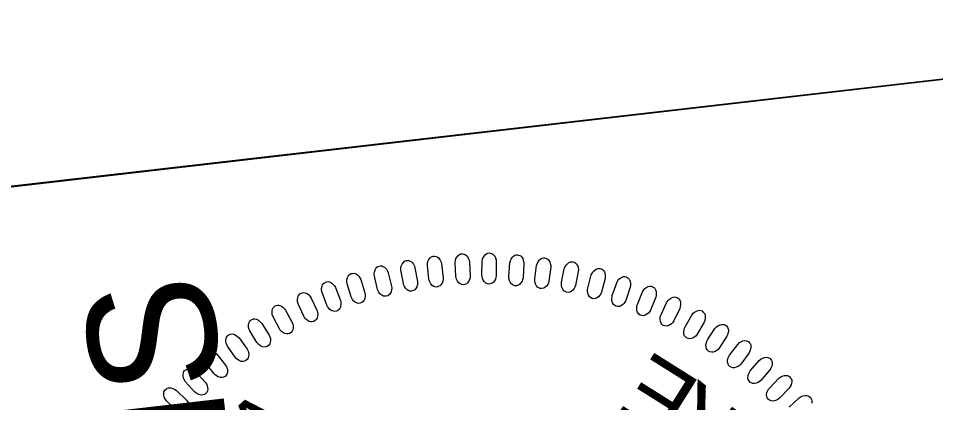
# Model space of a CAD drawing. Extents: x 477658 to 478938, y 495105 to 496902.
# Drawn here: x 477747.5 to 477830, y 496750.8 to 496785.4 of the extents above; entities that cross this region are included whole.
import ezdxf

# ---------------------------------------------------------------- set-up
doc = ezdxf.new("R2010")
doc.units = 0
for name, color, linetype in [('Sheet PE Seal Cell', 7, 'Continuous'), ('Sheet Plan CELL', 7, 'Continuous'), ('Sheet Sticker Incomplete CELL', 7, 'Continuous')]:
    doc.layers.add(name, color=color, linetype=linetype)

msp = doc.modelspace()

# ---------------------------------------------------------------- linework, layer by layer
at = {"layer": 'Sheet PE Seal Cell'}
for points in [[(477786.861, 496762.163), (477786.797, 496763.389), (477786.824, 496763.609), (477786.868, 496763.752), (477786.972, 496763.927), (477787.063, 496764.042), (477787.171, 496764.127), (477787.273, 496764.172), (477787.385, 496764.198), (477787.497, 496764.183), (477787.618, 496764.16), (477787.726, 496764.106), (477787.835, 496764.011), (477787.899, 496763.935), (477787.974, 496763.789), (477788.043, 496763.612), (477788.074, 496763.454), (477788.146, 496762.2), (477788.132, 496762.03), (477788.094, 496761.888), (477788.014, 496761.724), (477787.909, 496761.579), (477787.816, 496761.494), (477787.662, 496761.426), (477787.513, 496761.398), (477787.362, 496761.431), (477787.255, 496761.475), (477787.124, 496761.568), (477786.995, 496761.731), (477786.919, 496761.907), (477786.883, 496762.034)], [(477789.204, 496762.266), (477789.218, 496763.493), (477789.258, 496763.712), (477789.311, 496763.851), (477789.425, 496764.02), (477789.524, 496764.128), (477789.637, 496764.206), (477789.742, 496764.245), (477789.855, 496764.263), (477789.966, 496764.242), (477790.086, 496764.211), (477790.189, 496764.15), (477790.293, 496764.049), (477790.352, 496763.969), (477790.418, 496763.818), (477790.475, 496763.638), (477790.496, 496763.478), (477790.489, 496762.222), (477790.465, 496762.052), (477790.418, 496761.913), (477790.327, 496761.755), (477790.214, 496761.617), (477790.115, 496761.538), (477789.958, 496761.48), (477789.808, 496761.462), (477789.659, 496761.503), (477789.555, 496761.554), (477789.429, 496761.655), (477789.312, 496761.826), (477789.246, 496762.007), (477789.218, 496762.136)], [(477791.621, 496762.145), (477791.712, 496763.368), (477791.765, 496763.584), (477791.827, 496763.72), (477791.952, 496763.881), (477792.057, 496763.983), (477792.175, 496764.054), (477792.282, 496764.086), (477792.396, 496764.098), (477792.506, 496764.07), (477792.623, 496764.031), (477792.723, 496763.964), (477792.82, 496763.856), (477792.874, 496763.772), (477792.93, 496763.618), (477792.976, 496763.435), (477792.987, 496763.274), (477792.901, 496762.021), (477792.866, 496761.853), (477792.811, 496761.717), (477792.71, 496761.565), (477792.588, 496761.434), (477792.485, 496761.361), (477792.324, 496761.313), (477792.173, 496761.304), (477792.027, 496761.355), (477791.926, 496761.413), (477791.807, 496761.521), (477791.701, 496761.699), (477791.646, 496761.884), (477791.627, 496762.015)], [(477782.134, 496761.502), (477781.918, 496762.709), (477781.917, 496762.931), (477781.943, 496763.078), (477782.024, 496763.265), (477782.1, 496763.39), (477782.197, 496763.488), (477782.292, 496763.546), (477782.399, 496763.585), (477782.513, 496763.586), (477782.636, 496763.577), (477782.749, 496763.537), (477782.87, 496763.457), (477782.943, 496763.389), (477783.036, 496763.254), (477783.127, 496763.087), (477783.176, 496762.935), (477783.405, 496761.699), (477783.413, 496761.528), (477783.393, 496761.383), (477783.333, 496761.21), (477783.248, 496761.053), (477783.166, 496760.957), (477783.022, 496760.87), (477782.878, 496760.824), (477782.725, 496760.837), (477782.612, 496760.868), (477782.47, 496760.944), (477782.323, 496761.089), (477782.224, 496761.254), (477782.172, 496761.377)], [(477784.432, 496761.917), (477784.292, 496763.136), (477784.305, 496763.358), (477784.34, 496763.502), (477784.432, 496763.684), (477784.516, 496763.804), (477784.619, 496763.896), (477784.718, 496763.947), (477784.828, 496763.98), (477784.941, 496763.973), (477785.063, 496763.957), (477785.174, 496763.909), (477785.289, 496763.822), (477785.358, 496763.75), (477785.442, 496763.609), (477785.522, 496763.437), (477785.562, 496763.282), (477785.713, 496762.034), (477785.71, 496761.863), (477785.681, 496761.719), (477785.61, 496761.55), (477785.515, 496761.399), (477785.428, 496761.308), (477785.279, 496761.231), (477785.132, 496761.194), (477784.979, 496761.217), (477784.87, 496761.255), (477784.732, 496761.339), (477784.594, 496761.494), (477784.507, 496761.664), (477784.462, 496761.79)], [(477793.96, 496761.931), (477794.128, 496763.146), (477794.195, 496763.358), (477794.265, 496763.489), (477794.4, 496763.642), (477794.511, 496763.737), (477794.633, 496763.801), (477794.742, 496763.826), (477794.856, 496763.83), (477794.964, 496763.796), (477795.079, 496763.75), (477795.174, 496763.676), (477795.264, 496763.563), (477795.313, 496763.476), (477795.359, 496763.318), (477795.394, 496763.133), (477795.394, 496762.972), (477795.23, 496761.726), (477795.184, 496761.56), (477795.121, 496761.428), (477795.011, 496761.283), (477794.88, 496761.16), (477794.774, 496761.094), (477794.609, 496761.056), (477794.458, 496761.056), (477794.316, 496761.116), (477794.219, 496761.18), (477794.106, 496761.296), (477794.012, 496761.48), (477793.969, 496761.668), (477793.958, 496761.8)], [(477796.377, 496761.633), (477796.62, 496762.836), (477796.701, 496763.043), (477796.779, 496763.17), (477796.923, 496763.314), (477797.04, 496763.402), (477797.166, 496763.458), (477797.276, 496763.476), (477797.39, 496763.473), (477797.496, 496763.431), (477797.607, 496763.378), (477797.698, 496763.299), (477797.78, 496763.18), (477797.823, 496763.09), (477797.859, 496762.93), (477797.883, 496762.743), (477797.873, 496762.582), (477797.631, 496761.349), (477797.575, 496761.187), (477797.503, 496761.059), (477797.384, 496760.92), (477797.247, 496760.806), (477797.136, 496760.747), (477796.97, 496760.719), (477796.819, 496760.73), (477796.681, 496760.798), (477796.588, 496760.868), (477796.483, 496760.991), (477796.4, 496761.181), (477796.369, 496761.37), (477796.366, 496761.503)], [(477777.436, 496760.314), (477777.07, 496761.485), (477777.04, 496761.705), (477777.048, 496761.854), (477777.105, 496762.05), (477777.165, 496762.183), (477777.248, 496762.293), (477777.336, 496762.362), (477777.437, 496762.415), (477777.549, 496762.429), (477777.673, 496762.436), (477777.79, 496762.41), (477777.92, 496762.346), (477778.001, 496762.288), (477778.11, 496762.165), (477778.221, 496762.012), (477778.29, 496761.866), (477778.672, 496760.669), (477778.701, 496760.5), (477778.699, 496760.354), (477778.661, 496760.175), (477778.596, 496760.008), (477778.528, 496759.903), (477778.395, 496759.799), (477778.258, 496759.735), (477778.104, 496759.729), (477777.989, 496759.745), (477777.838, 496759.802), (477777.674, 496759.929), (477777.555, 496760.08), (477777.489, 496760.195)], [(477779.813, 496760.989), (477779.522, 496762.181), (477779.506, 496762.402), (477779.523, 496762.55), (477779.592, 496762.742), (477779.66, 496762.872), (477779.749, 496762.976), (477779.842, 496763.04), (477779.946, 496763.085), (477780.06, 496763.093), (477780.183, 496763.092), (477780.299, 496763.059), (477780.424, 496762.987), (477780.501, 496762.924), (477780.602, 496762.794), (477780.704, 496762.634), (477780.763, 496762.484), (477781.069, 496761.265), (477781.087, 496761.096), (477781.077, 496760.949), (477781.028, 496760.773), (477780.952, 496760.611), (477780.877, 496760.51), (477780.739, 496760.414), (477780.598, 496760.36), (477780.443, 496760.363), (477780.33, 496760.387), (477780.183, 496760.453), (477780.026, 496760.589), (477779.919, 496760.748), (477779.859, 496760.867)], [(477798.732, 496761.098), (477799.05, 496762.283), (477799.143, 496762.485), (477799.229, 496762.606), (477799.382, 496762.741), (477799.505, 496762.822), (477799.634, 496762.869), (477799.745, 496762.88), (477799.858, 496762.871), (477799.961, 496762.823), (477800.069, 496762.763), (477800.155, 496762.678), (477800.23, 496762.554), (477800.267, 496762.461), (477800.293, 496762.3), (477800.304, 496762.111), (477800.284, 496761.951), (477799.965, 496760.735), (477799.9, 496760.578), (477799.82, 496760.454), (477799.692, 496760.324), (477799.548, 496760.218), (477799.433, 496760.165), (477799.266, 496760.149), (477799.117, 496760.168), (477798.982, 496760.246), (477798.894, 496760.321), (477798.797, 496760.45), (477798.727, 496760.645), (477798.708, 496760.837), (477798.713, 496760.969)], [(477775.254, 496759.55), (477774.816, 496760.695), (477774.773, 496760.913), (477774.771, 496761.062), (477774.815, 496761.261), (477774.866, 496761.398), (477774.943, 496761.513), (477775.026, 496761.587), (477775.124, 496761.646), (477775.236, 496761.668), (477775.358, 496761.682), (477775.477, 496761.664), (477775.61, 496761.608), (477775.695, 496761.555), (477775.811, 496761.439), (477775.932, 496761.293), (477776.01, 496761.152), (477776.466, 496759.982), (477776.505, 496759.815), (477776.513, 496759.669), (477776.487, 496759.488), (477776.432, 496759.317), (477776.37, 496759.208), (477776.245, 496759.096), (477776.112, 496759.024), (477775.958, 496759.008), (477775.843, 496759.017), (477775.689, 496759.064), (477775.517, 496759.18), (477775.389, 496759.324), (477775.315, 496759.434)], [(477800.941, 496760.424), (477801.333, 496761.587), (477801.439, 496761.782), (477801.533, 496761.898), (477801.693, 496762.023), (477801.82, 496762.096), (477801.952, 496762.136), (477802.064, 496762.14), (477802.176, 496762.123), (477802.276, 496762.068), (477802.38, 496762.001), (477802.46, 496761.912), (477802.527, 496761.784), (477802.559, 496761.689), (477802.575, 496761.526), (477802.574, 496761.337), (477802.544, 496761.178), (477802.15, 496759.985), (477802.074, 496759.831), (477801.987, 496759.713), (477801.851, 496759.591), (477801.7, 496759.495), (477801.583, 496759.45), (477801.415, 496759.444), (477801.266, 496759.473), (477801.138, 496759.558), (477801.055, 496759.639), (477800.966, 496759.774), (477800.907, 496759.973), (477800.9, 496760.165), (477800.914, 496760.297)], [(477803.195, 496759.629), (477803.659, 496760.764), (477803.777, 496760.953), (477803.878, 496761.063), (477804.046, 496761.177), (477804.178, 496761.242), (477804.312, 496761.273), (477804.423, 496761.271), (477804.535, 496761.246), (477804.631, 496761.186), (477804.73, 496761.112), (477804.804, 496761.018), (477804.863, 496760.886), (477804.889, 496760.789), (477804.894, 496760.625), (477804.881, 496760.436), (477804.842, 496760.281), (477804.374, 496759.114), (477804.289, 496758.966), (477804.194, 496758.853), (477804.051, 496758.74), (477803.894, 496758.653), (477803.774, 496758.616), (477803.606, 496758.62), (477803.46, 496758.658), (477803.337, 496758.752), (477803.259, 496758.838), (477803.179, 496758.978), (477803.132, 496759.179), (477803.138, 496759.372), (477803.159, 496759.503)], [(477773.181, 496758.56), (477772.671, 496759.677), (477772.614, 496759.892), (477772.603, 496760.041), (477772.635, 496760.241), (477772.678, 496760.381), (477772.747, 496760.501), (477772.825, 496760.58), (477772.919, 496760.645), (477773.029, 496760.673), (477773.15, 496760.696), (477773.27, 496760.685), (477773.407, 496760.638), (477773.495, 496760.59), (477773.619, 496760.482), (477773.747, 496760.344), (477773.834, 496760.208), (477774.363, 496759.068), (477774.413, 496758.905), (477774.43, 496758.759), (477774.415, 496758.577), (477774.371, 496758.403), (477774.316, 496758.29), (477774.198, 496758.17), (477774.07, 496758.09), (477773.917, 496758.064), (477773.802, 496758.066), (477773.644, 496758.104), (477773.466, 496758.208), (477773.329, 496758.343), (477773.248, 496758.449)], [(477805.324, 496758.73), (477805.858, 496759.834), (477805.988, 496760.015), (477806.095, 496760.118), (477806.27, 496760.222), (477806.405, 496760.278), (477806.541, 496760.301), (477806.653, 496760.291), (477806.763, 496760.26), (477806.854, 496760.194), (477806.949, 496760.114), (477807.017, 496760.015), (477807.068, 496759.879), (477807.087, 496759.781), (477807.082, 496759.617), (477807.058, 496759.43), (477807.009, 496759.276), (477806.467, 496758.142), (477806.373, 496758), (477806.272, 496757.894), (477806.122, 496757.789), (477805.96, 496757.712), (477805.838, 496757.683), (477805.671, 496757.697), (477805.527, 496757.745), (477805.41, 496757.846), (477805.338, 496757.936), (477805.266, 496758.081), (477805.233, 496758.286), (477805.251, 496758.477), (477805.28, 496758.607)], [(477770.982, 496757.427), (477770.403, 496758.509), (477770.333, 496758.72), (477770.313, 496758.867), (477770.331, 496759.07), (477770.366, 496759.213), (477770.427, 496759.336), (477770.5, 496759.42), (477770.59, 496759.491), (477770.698, 496759.526), (477770.818, 496759.556), (477770.938, 496759.553), (477771.078, 496759.514), (477771.168, 496759.472), (477771.298, 496759.372), (477771.436, 496759.242), (477771.53, 496759.112), (477772.13, 496758.007), (477772.19, 496757.848), (477772.217, 496757.703), (477772.213, 496757.52), (477772.18, 496757.344), (477772.132, 496757.228), (477772.021, 496757.101), (477771.899, 496757.013), (477771.749, 496756.978), (477771.633, 496756.972), (477771.473, 496757), (477771.288, 496757.093), (477771.144, 496757.22), (477771.057, 496757.32)], [(477807.482, 496757.609), (477808.085, 496758.677), (477808.225, 496758.849), (477808.339, 496758.946), (477808.52, 496759.038), (477808.659, 496759.086), (477808.796, 496759.101), (477808.906, 496759.084), (477809.014, 496759.046), (477809.101, 496758.973), (477809.191, 496758.888), (477809.253, 496758.786), (477809.294, 496758.647), (477809.308, 496758.548), (477809.293, 496758.384), (477809.257, 496758.198), (477809.198, 496758.048), (477808.587, 496756.951), (477808.484, 496756.814), (477808.376, 496756.715), (477808.22, 496756.62), (477808.054, 496756.553), (477807.93, 496756.531), (477807.763, 496756.556), (477807.624, 496756.613), (477807.513, 496756.721), (477807.446, 496756.816), (477807.384, 496756.965), (477807.363, 496757.171), (477807.394, 496757.361), (477807.431, 496757.488)], [(477768.948, 496756.207), (477768.302, 496757.25), (477768.218, 496757.456), (477768.189, 496757.602), (477768.195, 496757.805), (477768.22, 496757.95), (477768.274, 496758.077), (477768.341, 496758.166), (477768.427, 496758.242), (477768.532, 496758.284), (477768.65, 496758.321), (477768.77, 496758.326), (477768.912, 496758.296), (477769.004, 496758.259), (477769.141, 496758.167), (477769.285, 496758.046), (477769.389, 496757.922), (477770.057, 496756.858), (477770.126, 496756.702), (477770.162, 496756.559), (477770.169, 496756.377), (477770.148, 496756.199), (477770.107, 496756.08), (477770.005, 496755.946), (477769.888, 496755.851), (477769.741, 496755.806), (477769.625, 496755.794), (477769.464, 496755.811), (477769.274, 496755.893), (477769.122, 496756.01), (477769.028, 496756.105)], [(477809.511, 496756.429), (477810.18, 496757.457), (477810.33, 496757.62), (477810.45, 496757.709), (477810.637, 496757.79), (477810.778, 496757.829), (477810.916, 496757.835), (477811.025, 496757.811), (477811.13, 496757.766), (477811.212, 496757.689), (477811.297, 496757.598), (477811.352, 496757.492), (477811.385, 496757.35), (477811.392, 496757.251), (477811.367, 496757.089), (477811.319, 496756.906), (477811.251, 496756.76), (477810.572, 496755.702), (477810.461, 496755.573), (477810.347, 496755.48), (477810.185, 496755.395), (477810.015, 496755.339), (477809.89, 496755.326), (477809.725, 496755.361), (477809.59, 496755.426), (477809.486, 496755.541), (477809.426, 496755.64), (477809.373, 496755.792), (477809.365, 496755.999), (477809.407, 496756.187), (477809.452, 496756.312)], [(477767.005, 496754.868), (477766.295, 496755.868), (477766.199, 496756.069), (477766.16, 496756.213), (477766.153, 496756.416), (477766.169, 496756.562), (477766.215, 496756.692), (477766.278, 496756.785), (477766.357, 496756.866), (477766.46, 496756.915), (477766.575, 496756.959), (477766.695, 496756.972), (477766.838, 496756.951), (477766.933, 496756.92), (477767.074, 496756.837), (477767.227, 496756.725), (477767.338, 496756.608), (477768.071, 496755.588), (477768.151, 496755.436), (477768.195, 496755.296), (477768.214, 496755.114), (477768.203, 496754.936), (477768.171, 496754.814), (477768.077, 496754.675), (477767.966, 496754.572), (477767.822, 496754.518), (477767.707, 496754.498), (477767.546, 496754.506), (477767.35, 496754.575), (477767.191, 496754.683), (477767.092, 496754.771)], [(477811.492, 496755.052), (477812.225, 496756.037), (477812.386, 496756.19), (477812.511, 496756.271), (477812.702, 496756.34), (477812.845, 496756.37), (477812.983, 496756.367), (477813.091, 496756.337), (477813.193, 496756.286), (477813.271, 496756.203), (477813.349, 496756.107), (477813.397, 496755.998), (477813.421, 496755.855), (477813.422, 496755.755), (477813.387, 496755.595), (477813.328, 496755.415), (477813.251, 496755.273), (477812.506, 496754.261), (477812.387, 496754.138), (477812.267, 496754.053), (477812.101, 496753.979), (477811.928, 496753.933), (477811.802, 496753.928), (477811.64, 496753.972), (477811.508, 496754.047), (477811.412, 496754.168), (477811.358, 496754.271), (477811.315, 496754.426), (477811.321, 496754.633), (477811.374, 496754.818), (477811.427, 496754.939)], [(477765.113, 496753.38), (477764.342, 496754.334), (477764.233, 496754.529), (477764.185, 496754.67), (477764.166, 496754.872), (477764.173, 496755.019), (477764.21, 496755.151), (477764.266, 496755.248), (477764.341, 496755.334), (477764.44, 496755.389), (477764.552, 496755.441), (477764.671, 496755.46), (477764.816, 496755.448), (477764.912, 496755.424), (477765.059, 496755.35), (477765.218, 496755.248), (477765.335, 496755.138), (477766.132, 496754.166), (477766.22, 496754.02), (477766.273, 496753.883), (477766.304, 496753.702), (477766.305, 496753.523), (477766.279, 496753.4), (477766.195, 496753.255), (477766.091, 496753.146), (477765.95, 496753.083), (477765.837, 496753.056), (477765.675, 496753.053), (477765.476, 496753.109), (477765.311, 496753.207), (477765.206, 496753.289)], [(477813.36, 496753.645), (477814.152, 496754.581), (477814.323, 496754.725), (477814.453, 496754.798), (477814.648, 496754.855), (477814.793, 496754.876), (477814.93, 496754.864), (477815.036, 496754.827), (477815.135, 496754.769), (477815.207, 496754.682), (477815.279, 496754.582), (477815.321, 496754.469), (477815.336, 496754.325), (477815.33, 496754.225), (477815.285, 496754.068), (477815.214, 496753.891), (477815.128, 496753.756), (477814.322, 496752.791), (477814.195, 496752.677), (477814.07, 496752.599), (477813.9, 496752.535), (477813.724, 496752.501), (477813.598, 496752.503), (477813.439, 496752.558), (477813.313, 496752.64), (477813.225, 496752.767), (477813.177, 496752.873), (477813.144, 496753.031), (477813.162, 496753.237), (477813.227, 496753.418), (477813.287, 496753.536)], [(477763.34, 496751.766), (477762.511, 496752.67), (477762.39, 496752.857), (477762.334, 496752.995), (477762.302, 496753.196), (477762.299, 496753.342), (477762.328, 496753.476), (477762.378, 496753.577), (477762.447, 496753.668), (477762.543, 496753.729), (477762.651, 496753.787), (477762.769, 496753.814), (477762.913, 496753.811), (477763.012, 496753.793), (477763.163, 496753.728), (477763.328, 496753.637), (477763.452, 496753.535), (477764.308, 496752.614), (477764.405, 496752.474), (477764.467, 496752.34), (477764.509, 496752.163), (477764.521, 496751.983), (477764.503, 496751.859), (477764.428, 496751.709), (477764.331, 496751.593), (477764.194, 496751.521), (477764.084, 496751.488), (477763.922, 496751.475), (477763.72, 496751.519), (477763.549, 496751.605), (477763.439, 496751.681)], [(477815.078, 496752.099), (477815.928, 496752.984), (477816.106, 496753.116), (477816.241, 496753.181), (477816.439, 496753.226), (477816.585, 496753.237), (477816.722, 496753.217), (477816.824, 496753.173), (477816.919, 496753.11), (477816.985, 496753.018), (477817.051, 496752.913), (477817.085, 496752.798), (477817.092, 496752.653), (477817.08, 496752.555), (477817.025, 496752.4), (477816.943, 496752.229), (477816.849, 496752.098), (477815.985, 496751.187), (477815.851, 496751.08), (477815.721, 496751.011), (477815.546, 496750.958), (477815.369, 496750.934), (477815.243, 496750.945), (477815.089, 496751.01), (477814.967, 496751.099), (477814.887, 496751.231), (477814.846, 496751.34), (477814.823, 496751.5), (477814.855, 496751.705), (477814.93, 496751.882), (477814.999, 496751.996)]]:
    msp.add_lwpolyline(points, close=True, dxfattribs=at)
for points in [[(477761.697, 496750.107), (477760.812, 496750.956), (477760.68, 496751.136), (477760.615, 496751.27), (477760.571, 496751.468), (477760.559, 496751.615), (477760.579, 496751.751), (477760.623, 496751.854), (477760.686, 496751.949), (477760.778, 496752.015), (477760.883, 496752.081), (477760.998, 496752.115), (477761.143, 496752.121), (477761.242, 496752.109), (477761.397, 496752.054), (477761.567, 496751.973), (477761.698, 496751.879), (477762.609, 496751.013), (477762.716, 496750.88), (477762.786, 496750.751)], [(477816.852, 496750.385), (477817.755, 496751.214), (477817.942, 496751.335), (477818.08, 496751.392), (477818.28, 496751.423), (477818.427, 496751.425), (477818.562, 496751.397), (477818.662, 496751.347), (477818.752, 496751.277), (477818.813, 496751.182), (477818.872, 496751.073), (477818.9, 496750.956), (477818.896, 496750.811), (477818.878, 496750.713)]]:
    msp.add_lwpolyline(points, dxfattribs=at)
at = {"layer": 'Sheet Plan CELL'}
for points in [[(477681.971, 496762.783), (477853.79, 495272.618), (478896.879, 495392.889), (478725.063, 496883.028)], [(477730.743, 496667.719), (477719.278, 496767.047), (477831.048, 496779.947), (477842.515, 496680.606)]]:
    msp.add_lwpolyline(points, close=True, dxfattribs=at)

# ---------------------------------------------------------------- texts
at = {"layer": 'Sheet PE Seal Cell'}
for s, height, rotation, p in [('E', 6.236, 147.84555, (477809.119, 496752.497)), ('K', 6.236, 140.99989, (477812.862, 496749.501)), ('A', 5.669, 42.25011, (477769.497, 496744.883))]:
    msp.add_text(s, height=height, rotation=rotation, dxfattribs=at).set_placement(p)
at = {"layer": 'Sheet Sticker Incomplete CELL'}
msp.add_text('INCOMPLETE PLANS', height=11.52, rotation=96.57729, dxfattribs=at).set_placement((477782.394, 496608.696))

doc.saveas('drawing.dxf')
